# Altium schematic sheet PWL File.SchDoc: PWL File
size A4; Organization: Altium Limited; Address1: L3, 12a Rodborough Rd; Address2: Frenchs Forest; Address3: NSW; Address4: Australia 2086; DocumentNumber: 1; SheetNumber: 1; SheetTotal: 1
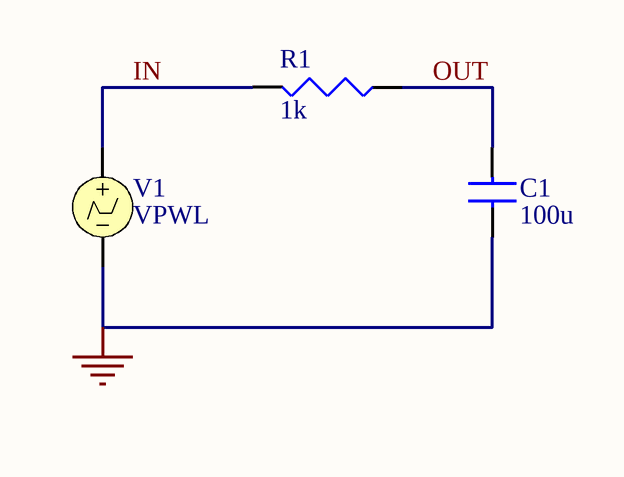
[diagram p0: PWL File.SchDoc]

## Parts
C1  value 100u  (hidden comment: *)
R1  value 1k  (hidden comment: *)
V1  VPWL

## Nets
GND: C1.2 V1.2
IN: R1.1(TOP) V1.1
OUT: C1.1 R1.2(BOT)

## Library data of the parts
C1 = CAP: Capacitor
R1 = RES: Resistor
V1 = VPWL: Piecewise Linear Voltage Source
